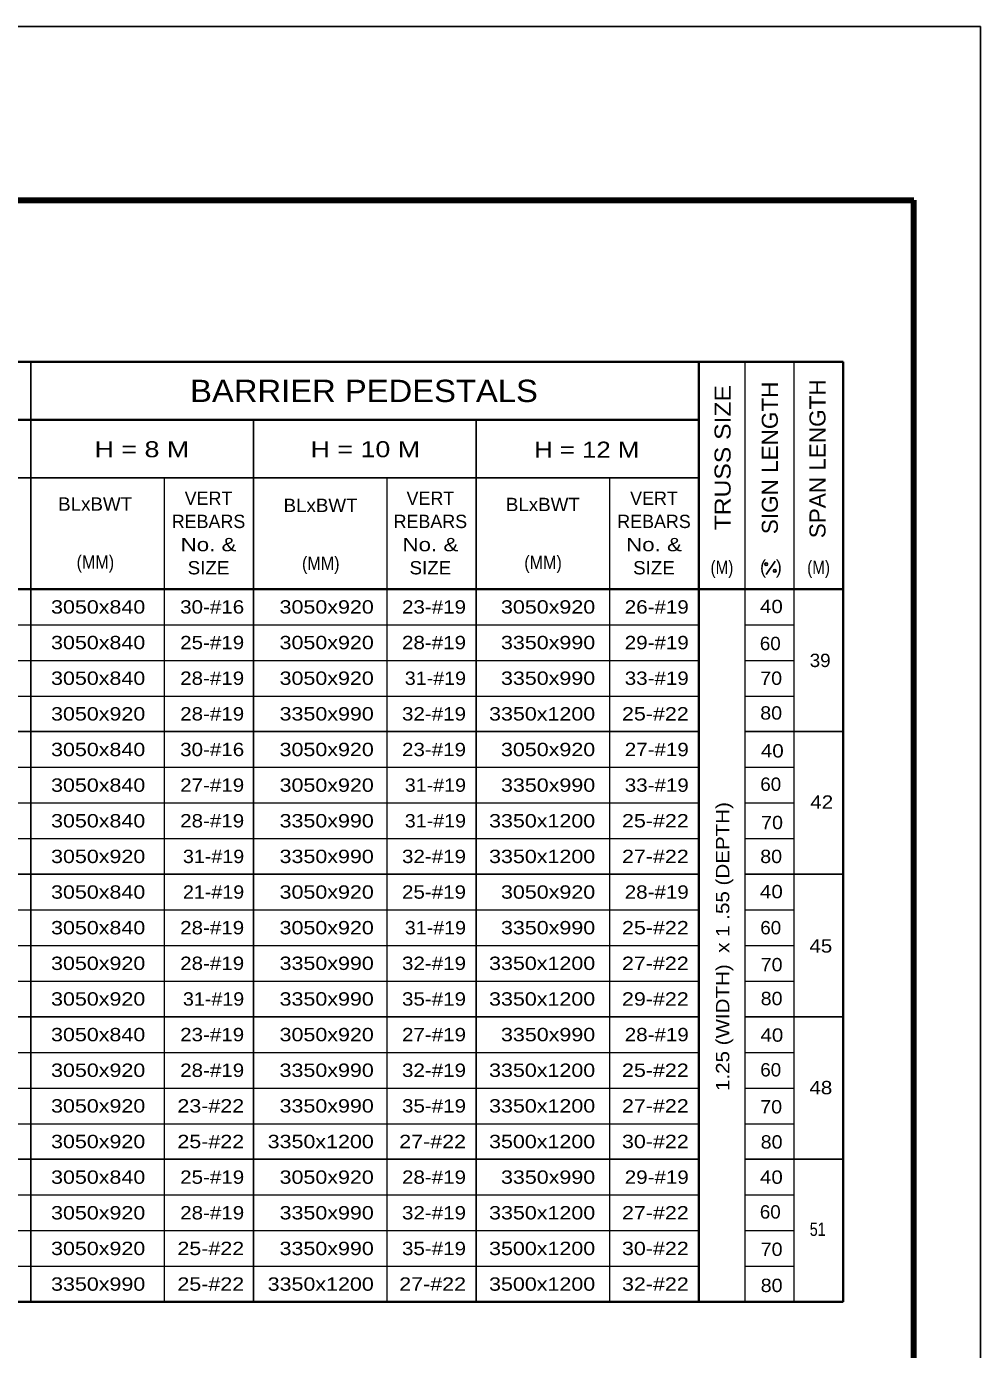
# Model space of a CAD drawing. Extents: x 312601.858 to 312602.699, y 144420.109 to 144420.703.
# Drawn here: x 312602.4847 to 312602.6989, y 144420.4063 to 144420.7033 of the extents above; entities that cross this region are included whole.
import ezdxf
from ezdxf.enums import TextEntityAlignment as Align

# ---------------------------------------------------------------- set-up
doc = ezdxf.new("R2010")
doc.units = 0
doc.header["$LTSCALE"] = 0.0012
doc.layers.add('1', color=7, linetype='Continuous', lineweight=13)
doc.layers.add('39', color=7, linetype='Continuous', lineweight=35)

msp = doc.modelspace()

# ---------------------------------------------------------------- linework, layer by layer
at = {"layer": '1', "lineweight": 35}
for p, q in [((312601.9277, 144420.628), (312602.6681, 144420.628)), ((312602.6357, 144420.4169), (312602.6357, 144420.628)), ((312602.6681, 144420.417), (312602.6681, 144420.628)), ((312601.9607, 144420.615), (312602.6357, 144420.615)), ((312601.9277, 144420.577), (312602.6681, 144420.577)), ((312601.9277, 144420.417), (312602.6681, 144420.417))]:
    msp.add_line(p, q, dxfattribs=at)
at = {"layer": '1', "lineweight": 25}
for p, q in [((312602.4857, 144420.417), (312602.4857, 144420.628)), ((312602.5357, 144420.417), (312602.5357, 144420.615)), ((312602.5857, 144420.417), (312602.5857, 144420.615)), ((312602.2907, 144420.602), (312602.6357, 144420.602)), ((312602.6508, 144420.5803), (312602.6528, 144420.5833)), ((312601.9609, 144420.545), (312602.6357, 144420.545)), ((312602.6461, 144420.545), (312602.6681, 144420.545)), ((312601.9609, 144420.513), (312602.6357, 144420.513)), ((312602.6461, 144420.513), (312602.6681, 144420.513)), ((312601.9609, 144420.481), (312602.6357, 144420.481)), ((312602.6461, 144420.481), (312602.6681, 144420.481)), ((312601.9609, 144420.449), (312602.6357, 144420.449)), ((312602.6461, 144420.449), (312602.6681, 144420.449))]:
    msp.add_line(p, q, dxfattribs=at)
at = {"layer": '1'}
for p, q in [((312602.6461, 144420.417), (312602.6461, 144420.628)), ((312602.6571, 144420.417), (312602.6571, 144420.628)), ((312602.5157, 144420.417), (312602.5157, 144420.602)), ((312602.5657, 144420.417), (312602.5657, 144420.602)), ((312602.6157, 144420.417), (312602.6157, 144420.602)), ((312601.9607, 144420.569), (312602.6357, 144420.569)), ((312602.6461, 144420.569), (312602.6571, 144420.569)), ((312601.9609, 144420.561), (312602.6357, 144420.561)), ((312602.6461, 144420.561), (312602.6571, 144420.561)), ((312601.9609, 144420.553), (312602.6357, 144420.553)), ((312602.6461, 144420.553), (312602.6571, 144420.553)), ((312601.9609, 144420.537), (312602.6357, 144420.537)), ((312602.6461, 144420.537), (312602.6571, 144420.537)), ((312601.9609, 144420.529), (312602.6357, 144420.529)), ((312602.6461, 144420.529), (312602.6571, 144420.529)), ((312601.9609, 144420.521), (312602.6357, 144420.521)), ((312602.6461, 144420.521), (312602.6571, 144420.521)), ((312601.9609, 144420.505), (312602.6357, 144420.505)), ((312602.6461, 144420.505), (312602.6571, 144420.505)), ((312601.9609, 144420.497), (312602.6357, 144420.497)), ((312602.6461, 144420.497), (312602.6571, 144420.497)), ((312601.9609, 144420.489), (312602.6357, 144420.489)), ((312602.6461, 144420.489), (312602.6571, 144420.489)), ((312601.9609, 144420.473), (312602.6357, 144420.473)), ((312602.6461, 144420.473), (312602.6571, 144420.473)), ((312601.9609, 144420.465), (312602.6357, 144420.465)), ((312602.6461, 144420.465), (312602.6571, 144420.465)), ((312601.9609, 144420.457), (312602.6357, 144420.457)), ((312602.6461, 144420.457), (312602.6571, 144420.457)), ((312601.9609, 144420.441), (312602.6357, 144420.441)), ((312602.6461, 144420.441), (312602.6571, 144420.441)), ((312601.9609, 144420.433), (312602.6357, 144420.433)), ((312602.6461, 144420.433), (312602.6571, 144420.433)), ((312601.9609, 144420.425), (312602.6357, 144420.425)), ((312602.6461, 144420.425), (312602.6571, 144420.425))]:
    msp.add_line(p, q, dxfattribs=at)
at = {"layer": '1', "lineweight": 25}
for centre in [(312602.6508, 144420.5826), (312602.6527, 144420.5811)]:
    msp.add_circle(centre, 0.0003, dxfattribs=at)
at = {"layer": '39', "lineweight": 25}
for p, q in [((312601.8579, 144420.7033), (312602.6989, 144420.7033)), ((312602.5736, 144420.6643), (312602.6839, 144420.6643)), ((312602.6839, 144420.6512), (312602.6839, 144420.6643))]:
    msp.add_line(p, q, dxfattribs=at)
msp.add_lwpolyline([(312601.8579, 144420.1093), (312602.6989, 144420.1093), (312602.6989, 144420.7033)], dxfattribs=at)
at = {"layer": '39', "lineweight": 158}
for points in [[(312601.9089, 144420.1243), (312602.6839, 144420.1243), (312602.6839, 144420.6643)], [(312601.9089, 144420.1245), (312601.9089, 144420.6643), (312602.6839, 144420.6643)]]:
    msp.add_lwpolyline(points, dxfattribs=at)

# ---------------------------------------------------------------- texts
at = {"layer": '1'}
for s, height, width, p in [('BARRIER PEDESTALS', 0.005, 1.1, (312602.5605, 144420.619)), ('H = 8 M', 0.0036, 1.25, (312602.51065, 144420.6066)), ('H = 10 M', 0.0036, 1.25, (312602.5608, 144420.6066)), ('H = 12 M', 0.0036, 1.2, (312602.6105, 144420.6065)), ('BLxBWT', 0.003, 1.05, (312602.50015, 144420.5946)), ('BLxBWT', 0.003, 1.05, (312602.55075, 144420.5943)), ('BLxBWT', 0.003, 1.05, (312602.60065, 144420.5945)), ('No. &', 0.003, 1.25, (312602.5256, 144420.5855)), ('No. &', 0.003, 1.25, (312602.5754, 144420.5855)), ('No. &', 0.003, 1.25, (312602.6256, 144420.5855)), ('(MM)', 0.003, 0.9, (312602.5002, 144420.5816)), ('SIZE', 0.003, 1.05, (312602.5256, 144420.5803)), ('(MM)', 0.003, 0.9, (312602.5508, 144420.5813)), ('SIZE', 0.003, 1.05, (312602.5754, 144420.5803)), ('(MM)', 0.003, 0.9, (312602.6007, 144420.5815)), ('SIZE', 0.003, 1.05, (312602.6256, 144420.5803)), ('(M)', 0.003, 0.85, (312602.64085, 144420.5804)), ('(M)', 0.003, 0.85, (312602.66255, 144420.5804)), ('40', 0.003, 1.15, (312602.65195, 144420.5716)), ('60', 0.003, 1.05, (312602.6517, 144420.5633)), ('39', 0.003, 1.05, (312602.6629, 144420.5595)), ('70', 0.003, 1.1, (312602.6519, 144420.5555)), ('80', 0.003, 1.1, (312602.6519, 144420.5477)), ('40', 0.003, 1.15, (312602.65215, 144420.5392)), ('60', 0.003, 1.05, (312602.6518, 144420.5317)), ('42', 0.003, 1.15, (312602.66325, 144420.5277)), ('70', 0.003, 1.1, (312602.6521, 144420.5231)), ('80', 0.003, 1.1, (312602.6519, 144420.5155)), ('40', 0.003, 1.15, (312602.65195, 144420.5076)), ('60', 0.003, 1.05, (312602.6518, 144420.4995)), ('45', 0.003, 1.15, (312602.66305, 144420.4954)), ('70', 0.003, 1.1, (312602.652, 144420.4912)), ('80', 0.003, 1.1, (312602.652, 144420.4836)), ('40', 0.003, 1.15, (312602.65205, 144420.4754)), ('60', 0.003, 1.05, (312602.6518, 144420.4676)), ('48', 0.003, 1.15, (312602.66305, 144420.4636)), ('70', 0.003, 1.1, (312602.6519, 144420.4593)), ('80', 0.003, 1.1, (312602.652, 144420.4514)), ('40', 0.003, 1.15, (312602.65195, 144420.4435)), ('60', 0.003, 1.05, (312602.6517, 144420.4357)), ('51', 0.003, 0.8, (312602.66235, 144420.4318)), ('70', 0.003, 1.1, (312602.652, 144420.4273)), ('80', 0.003, 1.1, (312602.652, 144420.4192))]:
    msp.add_text(s, height=height, dxfattribs=dict(at, width=width)).set_placement(p, align=Align.CENTER)
for s, height, width, p in [('TRUSS SIZE', 0.0036, 1.15, (312602.6428, 144420.6065)), ('SIGN LENGTH', 0.0036, 1.05, (312602.6534, 144420.60645)), ('SPAN LENGTH', 0.0036, 1.05, (312602.6641, 144420.60625)), ('1.25 (WIDTH)  x 1 .55 (DEPTH) ', 0.003, 1.15, (312602.6425, 144420.4974))]:
    msp.add_text(s, height=height, rotation=90, dxfattribs=dict(at, width=width)).set_placement(p, align=Align.CENTER)
for s, p in [('VERT', (312602.5256, 144420.5959)), ('VERT', (312602.5754, 144420.5959)), ('VERT', (312602.6256, 144420.5959)), ('REBARS', (312602.5256, 144420.5907)), ('REBARS', (312602.5754, 144420.5907)), ('REBARS', (312602.6256, 144420.5907)), ('(  )', (312602.65185, 144420.5805))]:
    msp.add_text(s, height=0.003, dxfattribs=at).set_placement(p, align=Align.CENTER)
for s, width, p in [('3050x840', 1.2, (312602.5114, 144420.5715)), ('30-#16', 1.15, (312602.5336, 144420.5715)), ('3050x920', 1.2, (312602.5627, 144420.5715)), ('23-#19', 1.15, (312602.5834, 144420.5715)), ('3050x920', 1.2, (312602.6124, 144420.5715)), ('26-#19', 1.15, (312602.6334, 144420.5715)), ('3050x840', 1.2, (312602.5114, 144420.5635)), ('25-#19', 1.15, (312602.5336, 144420.5635)), ('3050x920', 1.2, (312602.5627, 144420.5635)), ('28-#19', 1.15, (312602.5834, 144420.5635)), ('3350x990', 1.2, (312602.6124, 144420.5635)), ('29-#19', 1.15, (312602.6334, 144420.5635)), ('3050x840', 1.2, (312602.5114, 144420.5555)), ('28-#19', 1.15, (312602.5336, 144420.5555)), ('3050x920', 1.2, (312602.5627, 144420.5555)), ('31-#19', 1.1, (312602.5834, 144420.5555)), ('3350x990', 1.2, (312602.6124, 144420.5555)), ('33-#19', 1.15, (312602.6334, 144420.5555)), ('3050x920', 1.2, (312602.5114, 144420.5475)), ('28-#19', 1.15, (312602.5336, 144420.5475)), ('3350x990', 1.2, (312602.5627, 144420.5475)), ('32-#19', 1.15, (312602.5834, 144420.5475)), ('3350x1200', 1.2, (312602.6124, 144420.5475)), ('25-#22', 1.2, (312602.6334, 144420.5475)), ('3050x840', 1.2, (312602.5114, 144420.5395)), ('30-#16', 1.15, (312602.5336, 144420.5395)), ('3050x920', 1.2, (312602.5627, 144420.5395)), ('23-#19', 1.15, (312602.5834, 144420.5395)), ('3050x920', 1.2, (312602.6124, 144420.5395)), ('27-#19', 1.15, (312602.6334, 144420.5395)), ('3050x840', 1.2, (312602.5114, 144420.5315)), ('27-#19', 1.15, (312602.5336, 144420.5315)), ('3050x920', 1.2, (312602.5627, 144420.5315)), ('31-#19', 1.1, (312602.5834, 144420.5315)), ('3350x990', 1.2, (312602.6124, 144420.5315)), ('33-#19', 1.15, (312602.6334, 144420.5315)), ('3050x840', 1.2, (312602.5114, 144420.5235)), ('28-#19', 1.15, (312602.5336, 144420.5235)), ('3350x990', 1.2, (312602.5627, 144420.5235)), ('31-#19', 1.1, (312602.5834, 144420.5235)), ('3350x1200', 1.2, (312602.6124, 144420.5235)), ('25-#22', 1.2, (312602.6334, 144420.5235)), ('3050x920', 1.2, (312602.5114, 144420.5155)), ('31-#19', 1.1, (312602.5336, 144420.5155)), ('3350x990', 1.2, (312602.5627, 144420.5155)), ('32-#19', 1.15, (312602.5834, 144420.5155)), ('3350x1200', 1.2, (312602.6124, 144420.5155)), ('27-#22', 1.2, (312602.6334, 144420.5155)), ('3050x840', 1.2, (312602.5114, 144420.5075)), ('21-#19', 1.1, (312602.5336, 144420.5075)), ('3050x920', 1.2, (312602.5627, 144420.5075)), ('25-#19', 1.15, (312602.5834, 144420.5075)), ('3050x920', 1.2, (312602.6124, 144420.5075)), ('28-#19', 1.15, (312602.6334, 144420.5075)), ('3050x840', 1.2, (312602.5114, 144420.4995)), ('28-#19', 1.15, (312602.5336, 144420.4995)), ('3050x920', 1.2, (312602.5627, 144420.4995)), ('31-#19', 1.1, (312602.5834, 144420.4995)), ('3350x990', 1.2, (312602.6124, 144420.4995)), ('25-#22', 1.2, (312602.6334, 144420.4995)), ('3050x920', 1.2, (312602.5114, 144420.4915)), ('28-#19', 1.15, (312602.5336, 144420.4915)), ('3350x990', 1.2, (312602.5627, 144420.4915)), ('32-#19', 1.15, (312602.5834, 144420.4915)), ('3350x1200', 1.2, (312602.6124, 144420.4915)), ('27-#22', 1.2, (312602.6334, 144420.4915)), ('3050x920', 1.2, (312602.5114, 144420.4835)), ('31-#19', 1.1, (312602.5336, 144420.4835)), ('3350x990', 1.2, (312602.5627, 144420.4835)), ('35-#19', 1.15, (312602.5834, 144420.4835)), ('3350x1200', 1.2, (312602.6124, 144420.4835)), ('29-#22', 1.2, (312602.6334, 144420.4835)), ('3050x840', 1.2, (312602.5114, 144420.4755)), ('23-#19', 1.15, (312602.5336, 144420.4755)), ('3050x920', 1.2, (312602.5627, 144420.4755)), ('27-#19', 1.15, (312602.5834, 144420.4755)), ('3350x990', 1.2, (312602.6124, 144420.4755)), ('28-#19', 1.15, (312602.6334, 144420.4755)), ('3050x920', 1.2, (312602.5114, 144420.4675)), ('28-#19', 1.15, (312602.5336, 144420.4675)), ('3350x990', 1.2, (312602.5627, 144420.4675)), ('32-#19', 1.15, (312602.5834, 144420.4675)), ('3350x1200', 1.2, (312602.6124, 144420.4675)), ('25-#22', 1.2, (312602.6334, 144420.4675)), ('3050x920', 1.2, (312602.5114, 144420.4595)), ('23-#22', 1.2, (312602.5336, 144420.4595)), ('3350x990', 1.2, (312602.5627, 144420.4595)), ('35-#19', 1.15, (312602.5834, 144420.4595)), ('3350x1200', 1.2, (312602.6124, 144420.4595)), ('27-#22', 1.2, (312602.6334, 144420.4595)), ('3050x920', 1.2, (312602.5114, 144420.4515)), ('25-#22', 1.2, (312602.5336, 144420.4515)), ('3350x1200', 1.2, (312602.5627, 144420.4515)), ('27-#22', 1.2, (312602.5834, 144420.4515)), ('3500x1200', 1.2, (312602.6124, 144420.4515)), ('30-#22', 1.2, (312602.6334, 144420.4515)), ('3050x840', 1.2, (312602.5114, 144420.4435)), ('25-#19', 1.15, (312602.5336, 144420.4435)), ('3050x920', 1.2, (312602.5627, 144420.4435)), ('28-#19', 1.15, (312602.5834, 144420.4435)), ('3350x990', 1.2, (312602.6124, 144420.4435)), ('29-#19', 1.15, (312602.6334, 144420.4435)), ('3050x920', 1.2, (312602.5114, 144420.4355)), ('28-#19', 1.15, (312602.5336, 144420.4355)), ('3350x990', 1.2, (312602.5627, 144420.4355)), ('32-#19', 1.15, (312602.5834, 144420.4355)), ('3350x1200', 1.2, (312602.6124, 144420.4355)), ('27-#22', 1.2, (312602.6334, 144420.4355)), ('3050x920', 1.2, (312602.5114, 144420.4275)), ('25-#22', 1.2, (312602.5336, 144420.4275)), ('3350x990', 1.2, (312602.5627, 144420.4275)), ('35-#19', 1.15, (312602.5834, 144420.4275)), ('3500x1200', 1.2, (312602.6124, 144420.4275)), ('30-#22', 1.2, (312602.6334, 144420.4275)), ('3350x990', 1.2, (312602.5114, 144420.4195)), ('25-#22', 1.2, (312602.5336, 144420.4195)), ('3350x1200', 1.2, (312602.5627, 144420.4195)), ('27-#22', 1.2, (312602.5834, 144420.4195)), ('3500x1200', 1.2, (312602.6124, 144420.4195)), ('32-#22', 1.2, (312602.6334, 144420.4195))]:
    msp.add_text(s, height=0.003, dxfattribs=dict(at, width=width)).set_placement(p, align=Align.RIGHT)

doc.saveas('drawing.dxf')
